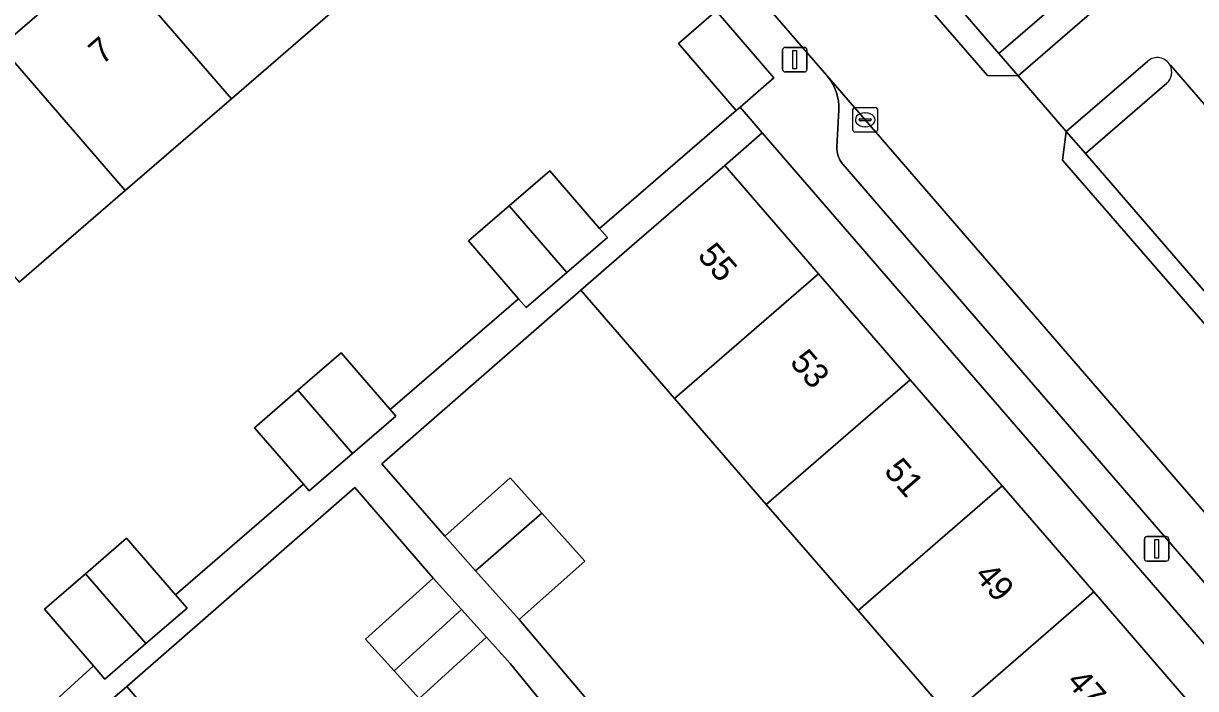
# Model space of a CAD drawing. Extents: x 160304 to 160955, y 383684 to 384161.
# Drawn here: x 160626.89 to 160674.59, y 383999.81 to 384026.86 of the extents above; entities that cross this region are included whole.
import ezdxf

# ---------------------------------------------------------------- set-up
doc = ezdxf.new("R2010")
doc.units = 0
for name, color, linetype in [('IMGEO_Erf', 7, 'Continuous'), ('IMGEO_Kolk', 7, 'Continuous'), ('IMGEO_Lichtmast', 7, 'Continuous'), ('IMGEO_Pand', 7, 'Continuous'), ('IMGEO_Pand_nummerreeks', 7, 'Continuous'), ('IMGEO_Parkeervlak_open', 7, 'Continuous'), ('IMGEO_Rijbaan_lokaal_open', 7, 'Continuous'), ('IMGEO_Voetpad_open', 7, 'Continuous')]:
    doc.layers.add(name, color=color, linetype=linetype)

msp = doc.modelspace()

# ---------------------------------------------------------------- linework, layer by layer
at = {"layer": 'IMGEO_Erf'}
msp.add_lwpolyline([(160606.643, 384013.229), (160608.608, 384010.922), (160613.017, 384014.733), (160617.334, 384018.464), (160621.652, 384022.196), (160625.969, 384025.927), (160630.287, 384029.658), (160634.604, 384033.39), (160638.922, 384037.122), (160643.346, 384040.945), (160641.322, 384043.252), (160641.094, 384043.055)], close=True, dxfattribs=at)
for points in [[(160624.643, 383996.089), (160629.734, 384000.735), (160627.748, 384003.035), (160629.417, 384004.477), (160631.087, 384005.919), (160633.074, 384003.619), (160638.278, 384008.116), (160636.292, 384010.415), (160638.055, 384011.938), (160639.818, 384013.461), (160641.807, 384011.159), (160647.033, 384015.666), (160645.004, 384018.014), (160646.656, 384019.441), (160648.308, 384020.868), (160650.336, 384018.521), (160655.896, 384023.324), (160653.539, 384026.046), (160655.073, 384027.375)], [(160639.668, 384027.529), (160635.348, 384023.798), (160631.03, 384020.069), (160626.712, 384016.339)], [(160708.32, 383997.939), (160711.652, 384000), (160713.157, 384000.931), (160717.995, 384003.923), (160722.832, 384006.915), (160727.787, 384009.979), (160726.422, 384012.115), (160706.936, 384000), (160687.05, 383987.636), (160676.351, 384000), (160656.955, 384022.413), (160655.424, 384021.087), (160659.239, 384016.681), (160662.975, 384012.366), (160666.712, 384008.05), (160670.447, 384003.736), (160673.681, 384000), (160674.183, 383999.42)], [(160664.592, 383998.665), (160663.435, 384000), (160660.855, 384002.979), (160657.118, 384007.294), (160653.381, 384011.608), (160649.566, 384016.013), (160641.469, 384008.942), (160644.036, 384006.002), (160646.695, 384008.381), (160647.987, 384006.937), (160649.726, 384004.992), (160647.066, 384002.614), (160651.51, 383997.373)], [(160650.353, 383996.335), (160646.71, 384000.816), (160645.735, 384001.893), (160642.989, 383999.407), (160641.972, 384000.53), (160640.813, 384001.81), (160643.559, 384004.297), (160640.377, 384007.988), (160631.1, 383999.887), (160634.906, 383995.478)]]:
    msp.add_lwpolyline(points, dxfattribs=at)
at = {"layer": 'IMGEO_Kolk'}
for p, q in [((160660.641, 384022.516), (160660.641, 384023.368)), ((160660.716, 384023.442), (160661.568, 384023.442)), ((160661.642, 384023.368), (160661.642, 384022.516)), ((160660.9, 384022.936), (160660.9, 384022.948)), ((160661.338, 384022.899), (160660.94, 384022.899)), ((160660.943, 384022.985), (160661.341, 384022.985)), ((160661.129, 384023.222), (160661.154, 384023.222)), ((160661.384, 384022.948), (160661.384, 384022.936)), ((160661.568, 384022.442), (160660.716, 384022.442)), ((160661.152, 384022.662), (160661.127, 384022.662))]:
    msp.add_line(p, q, dxfattribs=at)
for points in [[(160660.641, 384022.516), (160660.641, 384023.368)], [(160660.716, 384023.442), (160661.568, 384023.442)], [(160661.642, 384023.368), (160661.642, 384022.516)], [(160661.568, 384022.442), (160660.716, 384022.442)]]:
    msp.add_lwpolyline(points, dxfattribs=at)
for centre, radius, start, end in [((160660.718, 384023.366), 0.0765, 91.552, 178.448), ((160660.718, 384023.366), 0.0765, 91.552, 178.448), ((160661.566, 384023.366), 0.0765, 1.552, 88.448), ((160661.566, 384023.366), 0.0765, 1.552, 88.448), ((160660.94, 384022.945), 0.0403, 85.8775, 175.7526), ((160660.937, 384022.935), 0.0366, 178.938, 274.7102), ((160661.341, 384022.942), 0.043, 264.8664, 352.4533), ((160661.345, 384022.947), 0.0386, 1.7309, 96.639), ((160660.718, 384022.518), 0.0765, 181.552, 268.448), ((160660.718, 384022.518), 0.0765, 181.552, 268.448), ((160661.566, 384022.518), 0.0765, 271.552, 358.448), ((160661.566, 384022.518), 0.0765, 271.552, 358.448)]:
    msp.add_arc(centre, radius, start, end, dxfattribs=at)
for centre, major_axis, ratio, start_param, end_param in [((160661.128, 384022.942), (-0.387, 0.002), 0.722429, 4.712389, 7.853982), ((160661.153, 384022.942), (-0.39, 0.002), 0.717154, 1.570796, 4.712389)]:
    msp.add_ellipse(centre, major_axis=major_axis, ratio=ratio, start_param=start_param, end_param=end_param, dxfattribs=at)
at = {"layer": 'IMGEO_Lichtmast'}
for p, q in [((160657.782, 384024.987), (160657.782, 384025.787)), ((160657.782, 384025.787), (160657.782, 384024.987)), ((160657.882, 384025.887), (160658.672, 384025.887)), ((160658.672, 384025.887), (160657.882, 384025.887)), ((160658.772, 384025.787), (160658.772, 384024.987)), ((160658.772, 384024.987), (160658.772, 384025.787)), ((160658.672, 384024.887), (160657.882, 384024.887)), ((160657.882, 384024.887), (160658.672, 384024.887)), ((160672.505, 384005.088), (160672.505, 384005.888)), ((160672.505, 384005.888), (160672.505, 384005.088)), ((160672.605, 384005.988), (160673.395, 384005.988)), ((160673.395, 384005.988), (160672.605, 384005.988)), ((160673.495, 384005.888), (160673.495, 384005.088)), ((160673.495, 384005.088), (160673.495, 384005.888)), ((160673.395, 384004.988), (160672.605, 384004.988)), ((160672.605, 384004.988), (160673.395, 384004.988))]:
    msp.add_line(p, q, dxfattribs=at)
for points in [[(160658.202, 384025.762), (160658.352, 384025.762), (160658.352, 384025.012), (160658.202, 384025.012), (160658.202, 384025.762)], [(160672.925, 384005.863), (160673.075, 384005.863), (160673.075, 384005.113), (160672.925, 384005.113), (160672.925, 384005.863)]]:
    msp.add_lwpolyline(points, dxfattribs=at)
for centre, start, end in [((160657.882, 384025.787), 90, 180), ((160657.882, 384025.787), 90, 180), ((160658.672, 384025.787), 0, 90), ((160658.672, 384025.787), 360, 90), ((160657.882, 384024.987), 180, 270), ((160657.882, 384024.987), 180, 270), ((160658.672, 384024.987), 270, 0), ((160658.672, 384024.987), 270, 0), ((160672.605, 384005.888), 90, 180), ((160672.605, 384005.888), 90, 180), ((160673.395, 384005.888), 0, 90), ((160673.395, 384005.888), 360, 90), ((160672.605, 384005.088), 180, 270), ((160672.605, 384005.088), 180, 270), ((160673.395, 384005.088), 270, 0), ((160673.395, 384005.088), 270, 0)]:
    msp.add_arc(centre, 0.1, start, end, dxfattribs=at)
at = {"layer": 'IMGEO_Pand'}
for points in [[(160630.287, 384029.658), (160635.348, 384023.798), (160639.668, 384027.529), (160634.604, 384033.39)], [(160630.287, 384029.658), (160625.969, 384025.927), (160631.03, 384020.069), (160635.348, 384023.798)], [(160655.073, 384027.375), (160653.539, 384026.046), (160655.896, 384023.324), (160656.051, 384023.458), (160657.43, 384024.653)], [(160625.969, 384025.927), (160621.652, 384022.196), (160626.712, 384016.339), (160631.03, 384020.069)], [(160659.239, 384016.681), (160655.424, 384021.087), (160651.645, 384017.814), (160649.566, 384016.013), (160653.381, 384011.608)], [(160648.308, 384020.868), (160646.656, 384019.441), (160648.998, 384016.73), (160650.65, 384018.157), (160650.336, 384018.521)], [(160646.656, 384019.441), (160645.004, 384018.014), (160647.033, 384015.666), (160647.347, 384015.303), (160648.998, 384016.73)], [(160662.975, 384012.366), (160659.239, 384016.681), (160653.381, 384011.608), (160657.118, 384007.294)], [(160639.818, 384013.461), (160638.055, 384011.938), (160640.274, 384009.369), (160642.037, 384010.892), (160641.807, 384011.159)], [(160638.055, 384011.938), (160636.292, 384010.415), (160638.278, 384008.116), (160638.511, 384007.846), (160640.274, 384009.369)], [(160662.975, 384012.366), (160657.118, 384007.294), (160660.855, 384002.979), (160666.712, 384008.05)], [(160647.987, 384006.937), (160646.695, 384008.381), (160644.036, 384006.002), (160645.289, 384004.601)], [(160670.447, 384003.736), (160666.712, 384008.05), (160660.855, 384002.979), (160663.435, 384000), (160664.592, 383998.665), (160666.133, 384000)], [(160647.987, 384006.937), (160645.289, 384004.601), (160647.066, 384002.614), (160649.726, 384004.992)], [(160631.087, 384005.919), (160629.417, 384004.477), (160631.874, 384001.633), (160633.543, 384003.076), (160633.074, 384003.619)], [(160629.417, 384004.477), (160627.748, 384003.035), (160629.734, 384000.735), (160630.204, 384000.191), (160631.874, 384001.633)], [(160644.718, 384003.017), (160643.559, 384004.297), (160640.813, 384001.81), (160641.972, 384000.53)], [(160670.447, 384003.736), (160666.133, 384000), (160664.592, 383998.665), (160668.328, 383994.351), (160674.183, 383999.42), (160673.681, 384000)], [(160645.735, 384001.893), (160644.718, 384003.017), (160641.972, 384000.53), (160642.989, 383999.407)], [(160629.059, 383990.431), (160634.906, 383995.478), (160631.1, 383999.887), (160629.038, 383998.107), (160625.253, 383994.839)]]:
    msp.add_lwpolyline(points, close=True, dxfattribs=at)
at = {"layer": 'IMGEO_Parkeervlak_open'}
msp.add_lwpolyline([(160661.943, 384038.589), (160658.183, 384035.368), (160666.583, 384025.637), (160669.895, 384028.495), (160670.343, 384028.886)], close=True, dxfattribs=at)
for points in [[(160673.414, 384024.431), (160670.102, 384021.566), (160674.989, 384015.918), (160678.751, 384019.173), (160673.561, 384025.168), (160673.55, 384025.158)], [(160689.25, 383990.436), (160680.98, 384000), (160659.582, 384024.746), (160659.641, 384024.675), (160659.745, 384024.53), (160659.836, 384024.376), (160659.912, 384024.214), (160659.974, 384024.047), (160660.021, 384023.874), (160660.052, 384023.698), (160660.068, 384023.52), (160660.067, 384023.341), (160659.994, 384021.834), (160659.993, 384021.745), (160660.001, 384021.656), (160660.016, 384021.568), (160660.039, 384021.482), (160660.07, 384021.399), (160660.108, 384021.318), (160660.153, 384021.241), (160660.205, 384021.169), (160660.236, 384021.131), (160678.508, 384000), (160686.156, 383991.18)]]:
    msp.add_lwpolyline(points, dxfattribs=at)
msp.add_arc((160673.025, 384024.88), 0.594, 310.9003, 27.9079, dxfattribs=at)
at = {"layer": 'IMGEO_Rijbaan_lokaal_open'}
for points in [[(160673.55, 384025.158), (160673.561, 384025.168), (160678.751, 384019.173), (160692.299, 384027.507), (160688.256, 384034.009), (160682.556, 384030.486), (160672.68, 384041.948), (160669.159, 384038.895), (160647.166, 384064.33)], [(160688.132, 383999.685), (160687.658, 384000), (160687.129, 384000.428), (160686.548, 384001.032), (160677.923, 384011.231), (160669.173, 384021.297), (160669.327, 384022.462), (160667.365, 384024.732), (160666.113, 384024.749), (160658.5, 384033.527), (160657.69, 384034.466), (160653.963, 384031.243), (160659.582, 384024.746), (160680.98, 384000), (160689.25, 383990.436)], [(160670.673, 384027.595), (160667.365, 384024.732), (160669.327, 384022.462), (160672.638, 384025.328)]]:
    msp.add_lwpolyline(points, dxfattribs=at)
msp.add_arc((160673.026, 384024.877), 0.595, 28.1871, 130.695, dxfattribs=at)
at = {"layer": 'IMGEO_Voetpad_open'}
for points in [[(160649.083, 384045.896), (160638.722, 384057.851), (160639.112, 384058.226), (160638.265, 384059.201), (160637.108, 384060.567), (160636.048, 384059.616), (160638.02, 384057.244), (160648.87, 384044.696), (160655.889, 384036.556), (160657.69, 384034.466), (160658.5, 384033.527), (160666.113, 384024.749), (160667.365, 384024.732), (160666.583, 384025.637), (160658.183, 384035.368)], [(160670.102, 384021.566), (160669.327, 384022.462), (160669.173, 384021.297), (160677.923, 384011.231), (160678.359, 384011.504), (160677.437, 384012.58), (160677.721, 384012.757), (160675.301, 384015.555), (160674.989, 384015.918)]]:
    msp.add_lwpolyline(points, close=True, dxfattribs=at)
for points in [[(160678.508, 384000), (160660.236, 384021.131), (160660.205, 384021.169), (160660.153, 384021.241), (160660.108, 384021.318), (160660.07, 384021.399), (160660.039, 384021.482), (160660.016, 384021.568), (160660.001, 384021.656), (160659.993, 384021.745), (160659.994, 384021.834), (160660.067, 384023.341), (160660.068, 384023.52), (160660.052, 384023.698), (160660.021, 384023.874), (160659.974, 384024.047), (160659.912, 384024.214), (160659.836, 384024.376), (160659.745, 384024.53), (160659.641, 384024.675), (160659.582, 384024.746), (160653.963, 384031.243)], [(160669.895, 384028.495), (160666.583, 384025.637), (160667.365, 384024.732), (160670.673, 384027.595)], [(160655.073, 384027.375), (160657.43, 384024.653), (160656.051, 384023.458), (160656.955, 384022.413), (160676.351, 384000)], [(160672.638, 384025.328), (160669.327, 384022.462), (160670.102, 384021.566), (160673.414, 384024.431)], [(160651.51, 383997.373), (160647.066, 384002.614), (160645.289, 384004.601), (160644.036, 384006.002), (160641.469, 384008.942), (160649.566, 384016.013), (160651.645, 384017.814), (160655.424, 384021.087), (160656.955, 384022.413), (160656.051, 384023.458), (160655.896, 384023.324), (160650.336, 384018.521), (160650.65, 384018.157), (160648.998, 384016.73), (160647.347, 384015.303), (160647.033, 384015.666), (160641.807, 384011.159), (160642.037, 384010.892), (160640.274, 384009.369), (160638.511, 384007.846), (160638.278, 384008.116), (160633.074, 384003.619), (160633.543, 384003.076), (160631.874, 384001.633), (160630.204, 384000.191), (160629.734, 384000.735), (160624.643, 383996.089)], [(160629.038, 383998.107), (160631.1, 383999.887), (160640.377, 384007.988), (160643.559, 384004.297), (160644.718, 384003.017), (160645.735, 384001.893), (160646.71, 384000.816), (160650.353, 383996.335)]]:
    msp.add_lwpolyline(points, dxfattribs=at)
for centre, radius, start, end in [((160673.026, 384024.877), 0.595, 28.1871, 130.695), ((160673.025, 384024.88), 0.594, 310.9003, 27.9079)]:
    msp.add_arc(centre, radius, start, end, dxfattribs=at)

# ---------------------------------------------------------------- texts
at = {"layer": 'IMGEO_Pand_nummerreeks'}
for s, rotation, p in [('7', 40.8359, (160630.084, 384025.148)), ('55', 310.8956, (160654.282, 384017.396)), ('53', 310.8956, (160658.038, 384013.059)), ('51', 310.8956, (160661.869, 384008.636)), ('49', 310.8956, (160665.551, 384004.385)), ('47', 310.88, (160669.295, 384000.057))]:
    msp.add_text(s, height=1, rotation=rotation, dxfattribs=at).set_placement(p)

doc.saveas('drawing.dxf')
